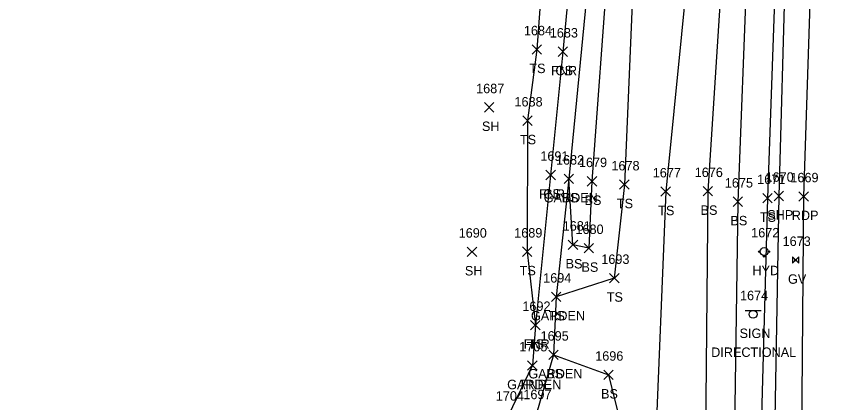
# Model space of a CAD drawing. Extents: x 1462089 to 1464015, y 730534 to 736144.
# Drawn here: x 1463038.1 to 1463210.3, y 735109.1 to 735190.8 of the extents above; entities that cross this region are included whole.
import ezdxf

# ---------------------------------------------------------------- set-up
doc = ezdxf.new("R2010")
doc.units = 0
for name, color, linetype in [('L_A', 7, 'Continuous'), ('L_I', 7, 'Continuous'), ('L_TIC', 7, 'Continuous'), ('LAPB', 7, 'Continuous'), ('LELB', 7, 'Continuous'), ('LFNC', 7, 'Continuous'), ('P_A', 7, 'Continuous'), ('P_I', 7, 'Continuous'), ('P_TIC', 7, 'Continuous'), ('PET', 7, 'Continuous'), ('PSP', 7, 'Continuous'), ('S_A', 7, 'Continuous'), ('S_C', 7, 'Continuous'), ('S_I', 7, 'Continuous'), ('SSGN', 7, 'Continuous'), ('U_A', 7, 'Continuous'), ('U_I', 7, 'Continuous'), ('UWFH', 7, 'Continuous'), ('UWV', 7, 'Continuous')]:
    doc.layers.add(name, color=color, linetype=linetype)

msp = doc.modelspace()

# ---------------------------------------------------------------- linework, layer by layer
at = {"layer": 'L_TIC'}
for points in [[(1463147.14, 735182.8), (1463149.14, 735184.8)], [(1463149.14, 735182.8), (1463147.14, 735184.8)], [(1463152.62, 735182.33), (1463154.62, 735184.33)], [(1463154.62, 735182.33), (1463152.62, 735184.33)], [(1463152.62, 735182.33), (1463154.62, 735184.33)], [(1463154.62, 735182.33), (1463152.62, 735184.33)], [(1463137.04, 735170.55), (1463139.04, 735172.55)], [(1463139.04, 735170.55), (1463137.04, 735172.55)], [(1463145.15, 735167.74), (1463147.15, 735169.74)], [(1463147.15, 735167.74), (1463145.15, 735169.74)], [(1463150.06, 735156.24), (1463152.06, 735158.24)], [(1463152.06, 735156.24), (1463150.06, 735158.24)], [(1463150.06, 735156.24), (1463152.06, 735158.24)], [(1463152.06, 735156.24), (1463150.06, 735158.24)], [(1463153.92, 735155.44), (1463155.92, 735157.44)], [(1463155.92, 735155.44), (1463153.92, 735157.44)], [(1463153.92, 735155.44), (1463155.92, 735157.44)], [(1463155.92, 735155.44), (1463153.92, 735157.44)], [(1463158.79, 735154.91), (1463160.79, 735156.91)], [(1463160.79, 735154.91), (1463158.79, 735156.91)], [(1463165.65, 735154.21), (1463167.65, 735156.21)], [(1463167.65, 735154.21), (1463165.65, 735156.21)], [(1463174.39, 735152.73), (1463176.39, 735154.73)], [(1463176.39, 735152.73), (1463174.39, 735154.73)], [(1463183.31, 735152.81), (1463185.31, 735154.81)], [(1463185.31, 735152.81), (1463183.31, 735154.81)], [(1463195.89, 735151.33), (1463197.89, 735153.33)], [(1463197.89, 735151.33), (1463195.89, 735153.33)], [(1463189.63, 735150.59), (1463191.63, 735152.59)], [(1463191.63, 735150.59), (1463189.63, 735152.59)], [(1463154.78, 735141.47), (1463156.78, 735143.47)], [(1463156.78, 735141.47), (1463154.78, 735143.47)], [(1463133.43, 735139.99), (1463135.43, 735141.99)], [(1463135.43, 735139.99), (1463133.43, 735141.99)], [(1463145.1, 735140.01), (1463147.1, 735142.01)], [(1463147.1, 735140.01), (1463145.1, 735142.01)], [(1463158.13, 735140.76), (1463160.13, 735142.76)], [(1463160.13, 735140.76), (1463158.13, 735142.76)], [(1463163.51, 735134.43), (1463165.51, 735136.43)], [(1463165.51, 735134.43), (1463163.51, 735136.43)], [(1463151.22, 735130.47), (1463153.22, 735132.47)], [(1463153.22, 735130.47), (1463151.22, 735132.47)], [(1463151.22, 735130.47), (1463153.22, 735132.47)], [(1463153.22, 735130.47), (1463151.22, 735132.47)], [(1463146.82, 735124.48), (1463148.82, 735126.48)], [(1463148.82, 735124.48), (1463146.82, 735126.48)], [(1463146.82, 735124.48), (1463148.82, 735126.48)], [(1463148.82, 735124.48), (1463146.82, 735126.48)], [(1463150.67, 735118.2), (1463152.67, 735120.2)], [(1463152.67, 735118.2), (1463150.67, 735120.2)], [(1463150.67, 735118.2), (1463152.67, 735120.2)], [(1463152.67, 735118.2), (1463150.67, 735120.2)], [(1463146.19, 735115.92), (1463148.19, 735117.92)], [(1463148.19, 735115.92), (1463146.19, 735117.92)], [(1463146.19, 735115.92), (1463148.19, 735117.92)], [(1463148.19, 735115.92), (1463146.19, 735117.92)], [(1463162.27, 735113.95), (1463164.27, 735115.95)], [(1463164.27, 735113.95), (1463162.27, 735115.95)]]:
    msp.add_lwpolyline(points, dxfattribs=at)
at = {"layer": 'LAPB'}
msp.add_lwpolyline([(1463167.4, 735325.3), (1463170.45, 735325.82), (1463171.1, 735321.79), (1463167.53, 735290.69), (1463162.51, 735237.9), (1463159.38, 735202.81), (1463154.92, 735156.44), (1463152.22, 735131.47), (1463151.67, 735119.2), (1463148.03, 735106.81), (1463145.63, 735103.62), (1463135.49, 735094.72), (1463135.43, 735100.44), (1463142.23, 735106.5), (1463147.19, 735116.92)], dxfattribs=at)
at = {"layer": 'LELB'}
for points in [[(1463231.13, 735553.2), (1463219.73, 735499.35), (1463218.06, 735477.58), (1463219.62, 735467.62), (1463217.32, 735453.77), (1463213, 735412.76), (1463211.19, 735365.65), (1463207.57, 735319.53), (1463204.72, 735284.77), (1463200.75, 735235.74), (1463198.61, 735200.32), (1463196.89, 735152.33), (1463195.26, 735093.48), (1463195.54, 735049.62), (1463191.11, 735032.92), (1463186.38, 735026.08), (1463169.01, 735015.93), (1463152.22, 735012.41), (1463106.31, 735015.09), (1463078.36, 735017.99), (1463050.15, 735020.48), (1463042.67, 735031.39), (1463039.52, 735041.31), (1463038.07, 735043.85)], [(1463168.22, 735472.13), (1463194.09, 735467.08), (1463204.5, 735461.37), (1463207.65, 735460.85), (1463210.02, 735460.87), (1463209.38, 735453.25), (1463206.15, 735413.21), (1463198.86, 735360.83), (1463200.51, 735352.21), (1463198.19, 735326.29), (1463191.41, 735287.36), (1463190.02, 735236.66), (1463187.37, 735201.98), (1463184.31, 735153.81), (1463183.76, 735094.85), (1463186.63, 735049.61), (1463185.07, 735027.27)], [(1463200.51, 735352.21), (1463188.51, 735345.73), (1463175.93, 735332.26), (1463174.46, 735321.85), (1463171.9, 735289.98), (1463166.8, 735237.02), (1463163.25, 735203), (1463159.79, 735155.91), (1463159.13, 735141.76), (1463155.78, 735142.47), (1463154.92, 735156.44)], [(1463195.31, 735342.63), (1463177.96, 735331.52), (1463179.03, 735321.72), (1463176.7, 735289.65), (1463172.84, 735235.98), (1463168.65, 735201.94), (1463166.65, 735155.21), (1463164.51, 735135.43), (1463152.22, 735131.47)], [(1463195.31, 735342.63), (1463193.2, 735325.86), (1463186.6, 735288.03), (1463181.92, 735235.07), (1463180.43, 735204.08), (1463175.39, 735153.73), (1463173.09, 735096.91), (1463173.36, 735074.38), (1463178.2, 735048.04), (1463168.64, 735020.12)], [(1463161.69, 735327.71), (1463158.15, 735291.08), (1463154.38, 735253.36), (1463150.33, 735213.5), (1463148.14, 735183.8), (1463146.15, 735168.74), (1463146.1, 735141.01), (1463147.82, 735125.48)], [(1463192.57, 735200.99), (1463190.63, 735151.59), (1463189.79, 735093.98), (1463193.34, 735049.55), (1463191.11, 735032.92), (1463185.07, 735027.27), (1463168.64, 735020.12), (1463152.72, 735019.65), (1463107.01, 735023.84), (1463078.95, 735030.11), (1463052.74, 735030.13), (1463045.89, 735042.21), (1463044.09, 735045.8)], [(1463153.62, 735183.33), (1463151.06, 735157.24)], [(1463151.67, 735119.2), (1463163.27, 735114.95), (1463173.36, 735074.38), (1463169.37, 735065.69), (1463165.46, 735056.72), (1463157.79, 735051.5), (1463145.5, 735047.5), (1463130.67, 735047.07), (1463113.56, 735049.6), (1463112.62, 735060.24), (1463120.44, 735076.35)]]:
    msp.add_lwpolyline(points, dxfattribs=at)
at = {"layer": 'LFNC'}
for points in [[(1463157.47, 735223.62), (1463153.62, 735183.33)], [(1463151.06, 735157.24), (1463147.82, 735125.48), (1463147.19, 735116.92)]]:
    msp.add_lwpolyline(points, dxfattribs=at)
at = {"layer": 'P_TIC'}
for points in [[(1463198.32, 735151.81), (1463200.32, 735153.81)], [(1463200.32, 735151.81), (1463198.32, 735153.81)], [(1463203.55, 735151.7), (1463205.55, 735153.7)], [(1463205.55, 735151.7), (1463203.55, 735153.7)]]:
    msp.add_lwpolyline(points, dxfattribs=at)
at = {"layer": 'PET'}
msp.add_lwpolyline([(1463231.54, 735502.9), (1463225.18, 735462.15), (1463220.16, 735414.55), (1463216.67, 735366.03), (1463213.86, 735320.54), (1463211.78, 735284.44), (1463208.46, 735235.21), (1463206.06, 735200.07), (1463204.55, 735152.7), (1463204.01, 735093.5), (1463203.51, 735049.66), (1463202.51, 734992.12), (1463204, 734960.4), (1463204.3, 734923.21), (1463204.35, 734878.71), (1463204.37, 734841.23), (1463204.71, 734797.84), (1463205.78, 734749.61)], dxfattribs=at)
at = {"layer": 'PSP'}
msp.add_lwpolyline([(1463227.64, 735503.57), (1463221.36, 735462.15), (1463215.73, 735410.01), (1463213.65, 735365.72), (1463210.04, 735320.15), (1463207.12, 735284.94), (1463203.09, 735235.35), (1463200.68, 735200.73), (1463199.32, 735152.81), (1463198.28, 735093.98), (1463198.26, 735049.48), (1463197.66, 735039.49), (1463197.75, 734989.04), (1463198.92, 734978.2), (1463198.51, 734929.67), (1463198.65, 734878.82), (1463198.97, 734841.36), (1463199.84, 734798.03), (1463200.23, 734750.21)], dxfattribs=at)
at = {"layer": 'SSGN'}
for p, q in [((1463192.21, 735128.6), (1463195.54, 735128.6)), ((1463193.86, 735127.77), (1463193.86, 735127.77))]:
    msp.add_line(p, q, dxfattribs=at)
msp.add_circle((1463193.86, 735127.77), 0.833, dxfattribs=at)
at = {"layer": 'UWFH'}
msp.add_line((1463196.2, 735141.04), (1463196.2, 735141.04), dxfattribs=at)
for centre, radius in [((1463196.2, 735141.04), 0.833), ((1463195.2, 735141.04), 0.167), ((1463196.2, 735140.04), 0.167), ((1463197.2, 735141.04), 0.167)]:
    msp.add_circle(centre, radius, dxfattribs=at)
at = {"layer": 'UWV'}
for p, q in [((1463202.17, 735139.9), (1463203.5, 735138.56)), ((1463203.5, 735139.9), (1463202.17, 735138.56))]:
    msp.add_line(p, q, dxfattribs=at)
for points in [[(1463202.17, 735139.9), (1463202.17, 735138.56)], [(1463203.5, 735138.56), (1463203.5, 735139.9)]]:
    msp.add_lwpolyline(points, dxfattribs=at)
msp.add_circle((1463202.84, 735139.23), 0.167, dxfattribs=at)

# ---------------------------------------------------------------- texts
at = {"layer": 'L_A'}
for s, p in [('TS', (1463146.55, 735178.8)), ('FNR', (1463151.15, 735178.33)), ('CS', (1463152.06, 735178.33)), ('SH', (1463136.53, 735166.55)), ('TS', (1463144.56, 735163.74)), ('FNR', (1463148.59, 735152.24)), ('CS', (1463149.5, 735152.24)), ('GARDEN', (1463149.59, 735151.44)), ('BS', (1463153.37, 735151.44)), ('BS', (1463158.23, 735150.91)), ('TS', (1463165.06, 735150.21)), ('TS', (1463173.8, 735148.73)), ('BS', (1463182.76, 735148.81)), ('BS', (1463189.07, 735146.59)), ('TS', (1463195.3, 735147.33)), ('SH', (1463132.92, 735135.99)), ('TS', (1463144.51, 735136.01)), ('BS', (1463154.22, 735137.47)), ('BS', (1463157.57, 735136.76)), ('TS', (1463162.92, 735130.43)), ('GARDEN', (1463146.89, 735126.47)), ('TS', (1463150.63, 735126.47)), ('FNR', (1463145.36, 735120.48)), ('TS', (1463146.23, 735120.48)), ('GARDEN', (1463146.34, 735114.2)), ('BS', (1463150.12, 735114.2)), ('GARDEN', (1463141.86, 735111.92)), ('FNR', (1463144.72, 735111.92)), ('BS', (1463161.71, 735109.95))]:
    msp.add_text(s, height=2, dxfattribs=at).set_placement(p)
at = {"layer": 'L_I'}
for s, p in [('1684', (1463145.4, 735186.8)), ('1683', (1463150.88, 735186.33)), ('1683', (1463150.88, 735186.33)), ('1687', (1463135.3, 735174.55)), ('1688', (1463143.41, 735171.74)), ('1691', (1463148.88, 735160.24)), ('1691', (1463148.88, 735160.24)), ('1682', (1463152.18, 735159.44)), ('1682', (1463152.18, 735159.44)), ('1679', (1463157.04, 735158.91)), ('1678', (1463163.91, 735158.21)), ('1677', (1463172.65, 735156.73)), ('1676', (1463181.52, 735156.81)), ('1671', (1463194.72, 735155.33)), ('1675', (1463187.89, 735154.59)), ('1681', (1463153.61, 735145.47)), ('1680', (1463156.3, 735144.76)), ('1690', (1463131.61, 735143.99)), ('1689', (1463143.35, 735144.01)), ('1693', (1463161.77, 735138.43)), ('1694', (1463149.48, 735134.47)), ('1694', (1463149.48, 735134.47)), ('1692', (1463145.08, 735128.48)), ('1692', (1463145.08, 735128.48)), ('1695', (1463148.93, 735122.2)), ('1695', (1463148.93, 735122.2)), ('1705', (1463144.42, 735119.92)), ('1705', (1463144.42, 735119.92)), ('1696', (1463160.48, 735117.95)), ('1704', (1463139.46, 735109.5)), ('1697', (1463145.29, 735109.81)), ('1697', (1463145.29, 735109.81))]:
    msp.add_text(s, height=2, dxfattribs=at).set_placement(p)
at = {"layer": 'P_A'}
for s, p in [('SHP', (1463196.86, 735147.81)), ('RDP', (1463202.04, 735147.7))]:
    msp.add_text(s, height=2, dxfattribs=at).set_placement(p)
at = {"layer": 'P_I'}
for s, p in [('1670', (1463196.5, 735155.81)), ('1669', (1463201.75, 735155.7))]:
    msp.add_text(s, height=2, dxfattribs=at).set_placement(p)
at = {"layer": 'S_A'}
msp.add_text('SIGN', height=2, dxfattribs=at).set_placement((1463191, 735122.75))
at = {"layer": 'S_C'}
msp.add_text('DIRECTIONAL', height=2, dxfattribs=at).set_placement((1463185, 735118.75))
at = {"layer": 'S_I'}
msp.add_text('1674', height=2, dxfattribs=at).set_placement((1463191.1, 735130.75))
at = {"layer": 'U_A'}
for s, p in [('HYD', (1463193.72, 735136.04)), ('GV', (1463201.24, 735134.23))]:
    msp.add_text(s, height=2, dxfattribs=at).set_placement(p)
at = {"layer": 'U_I'}
for s, p in [('1672', (1463193.46, 735144.04)), ('1673', (1463200.1, 735142.23))]:
    msp.add_text(s, height=2, dxfattribs=at).set_placement(p)

doc.saveas('drawing.dxf')
